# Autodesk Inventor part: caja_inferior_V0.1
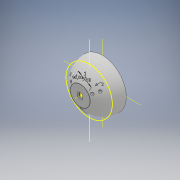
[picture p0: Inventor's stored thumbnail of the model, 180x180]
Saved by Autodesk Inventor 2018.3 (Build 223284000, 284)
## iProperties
Created: 2019-04
Part Number: caja_inferior_V0.1
Material: Generic
Document SubType Name: Modeling
Designer: Antonio Gordillo
Density: 1 g/cm^3
Appearance: Default
Author: Antonio Gordillo
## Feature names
1. Extrusion1
2. Revolution3
3. Revolution6
4. Extrusion2
5. Sweep1
6. Circular Pattern1
7. Fillet1
8. Extrusion3
## Parameters: largo_pi = 85 mm, ancho_pi = 56 mm, d9 = 3 mm, diam_tornillo_pi = 2.75 mm, d11 = 3.5 mm, d12 = 3.5 mm, d15 = 58 mm, d18 = 49 mm, d21 = 55 mm, d22 = 4 mm, d23 = 0, d24 = 7 mm, d25 = 180 deg, d26 = 77 mm, d27 = 9 mm, d30 = 180 deg, d33 = 5 mm, d35 = 0, d39 = 0, d40 = 0, d41 = 0, d42 = 25 mm, d43 = 90 deg, d45 = 360 deg, d47 = 2 mm, d48 = 15 mm, d49 = 16 mm, d51 = 0, d54 = 0, d55 = -23.5 mm, d56 = 0, d57 = 0, d58 = 1 mm, d59 = 0, d60 = 180 deg, d70 = 3 mm, d71 = 90 deg, d73 = 10 mm, d74 = 2 mm
